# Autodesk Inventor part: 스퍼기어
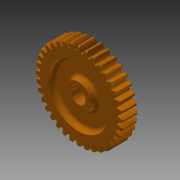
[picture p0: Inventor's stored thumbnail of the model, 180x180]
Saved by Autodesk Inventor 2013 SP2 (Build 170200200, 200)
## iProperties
Created: 2019-01
Part Number: 스퍼기어
Material: 강철, 주조
Document SubType Name: Modeling
Designer: mduedu
Density: 7.85 g/cm^3
Mass: 107.477 g
Surface Area: 168.408 cm^2
Volume: 39.6595 cm^3
Author: mduedu
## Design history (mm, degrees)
sketch "스케치1"
  geometry: C1 r 33.5 at (0, 0); C2 r 36 at (0, 0); C3 r 38 at (0, 0); 1 further point
  constraints: 3 centre point, 3 coincident
  dimensions: "d0" = 67 diameter of C1; "d2" = 72 diameter of C2; "d3" = 76 diameter of C3
extrude "돌출1" new body sketch "스케치1" distance "d4" = 14; taper "d5" = 0 deg
sketch "스케치2"
  geometry: L1 (0, 0)-(-38, 0); L2 (0, 0)-(0, 38); L3 (-0.57, 0)-(-0.57, 37.996); L4 (-1.57, 0)-(-1.57, 35.966); L5 (-2.07, 0)-(-2.07, 33.436); A1 r 38 centre (0, 0) between (-38, 0) and (0, 38) reference; A2 r 9.246 centre (7.162, 32.926) between (-0.57, 37.996) and (-2.07, 33.436); A3 r 9.246 centre (-7.162, 32.926) between (2.07, 33.436) and (0.57, 37.996); A4 r 33.5 centre (0, 0) between (2.07, 33.436) and (-2.07, 33.436); A5 r 38 centre (0, 0) between (0.57, 37.996) and (-0.57, 37.996); 2 further points
  constraints: 12 point on circle, 10 end point, 4 centre point, 3 parallel, 3 symmetric about line, 2 coincident, 1 horizontal, 1 perpendicular, 5 other
  dimensions: "d6" = 0.5 distance between parallel lines of L4 L5; "d8" = 1 distance between parallel lines of L3 L4; "d9" = 1.57 distance between parallel lines of L2 L4
extrude "돌출2" join sketch "스케치2" stored distance "d10" = 14; taper "d11" = 0 deg
chamfer "모따기1" distance "d12" = 1; stored, may be unused: second distance "d13" = 2, angle "d14" = 45 deg
fillet "모깎기1" dims "d15" = 0.5
sketch "스케치3"
  geometry: C1 r 11 at (0, 0); 1 further point
  constraints: 1 centre point, 1 coincident
  dimensions: "d19" = 22 diameter of C1
extrude "돌출3" join sketch "스케치3" distance "d20" = 6; taper "d21" = 0 deg
sketch "스케치4"
  geometry: C1 r 11 at (0, 0); C2 r 26 at (0, 0); 1 further point
  constraints: 2 centre point, 2 coincident
  dimensions: "d23" = 22 diameter of C1; "d24" = 52 diameter of C2
extrude "돌출4" cut sketch "스케치4" distance "d25" = 5; taper "d26" = 0 deg
fillet "모깎기3" dims "d27" = 3
node "작업 평면1"
sketch "스케치5" dims "d28" = 60
  geometry: C1 r 1.5 at (0, 30); 2 further points
  constraints: 2 vertical alignment, 1 centre point, 1 coincident, 2 other
  dimensions: "d29" = 3 diameter of C1
extrude "돌출5" join sketch "스케치5" distance "d30" = 0.5; taper "d31" = 0 deg
sketch "스케치6"
  geometry: L1 (-2, 5.657)-(2, 5.657); L2 (2, 5.657)-(2, 7.8); L3 (2, 7.8)-(-2, 7.8); L4 (-2, 7.8)-(-2, 5.657); A1 r 6 centre (0, 0) between (-2, 5.657) and (2, 5.657); 1 further point
  constraints: 8 end point, 2 parallel, 2 point on circle, 1 centre point, 1 coincident, 1 horizontal, 1 perpendicular
  dimensions: "d32" = 13.8 dimension on A1 L3; "d34" = 4 distance of L2.end L3.end; "d35" = 12 diameter of A1
extrude "돌출6" cut sketch "스케치6" stored distance "d36" = 0.5; taper "d37" = 0 deg
chamfer "모따기2" distance "d38" = 1; stored, may be unused: second distance "d39" = 2, angle "d40" = 45 deg
feature "면 이동1"
node "솔리드1"
pattern_circular "원형 패턴1" dims "d17" = 360 deg
mirror "대칭1"
